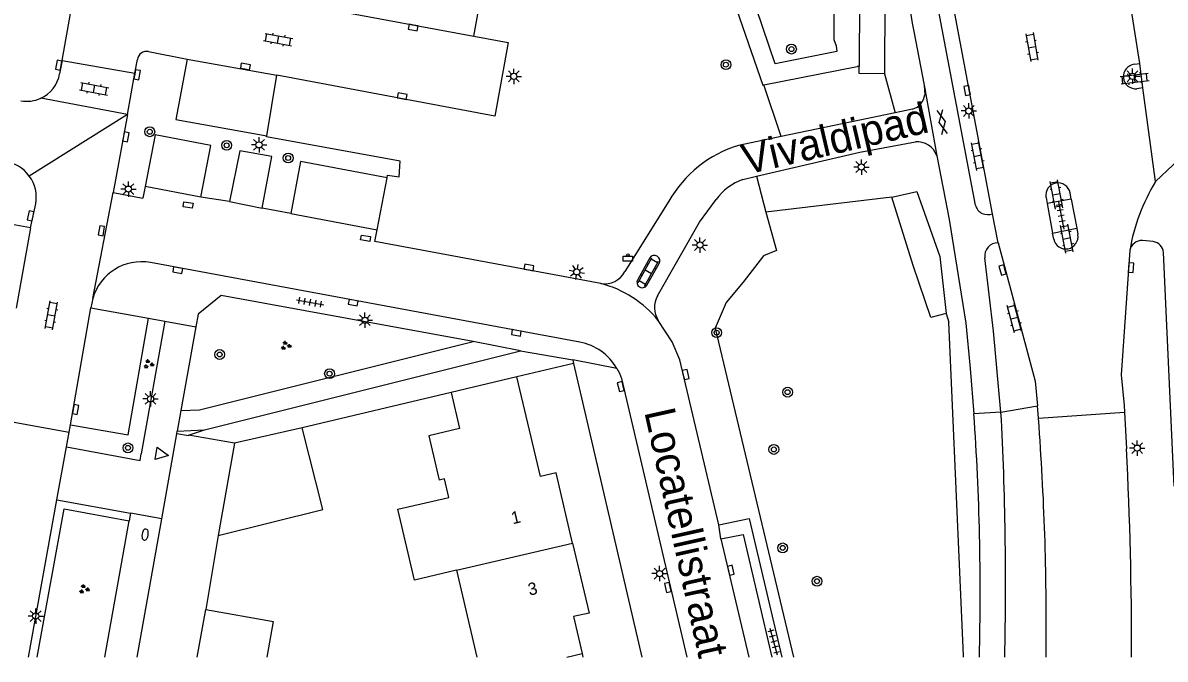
# Model space of a CAD drawing. Extents: x 133000 to 136000, y 400500 to 403500.
# Drawn here: x 133772.5 to 133865.4, y 400499.8 to 400551.6 of the extents above; entities that cross this region are included whole.
import ezdxf

# ---------------------------------------------------------------- set-up
doc = ezdxf.new("R2010")
doc.units = 0
for name, color, linetype in [('gg-afsc-erfafscheiding', 7, 'Continuous'), ('gg-afsc-muur', 7, 'Continuous'), ('gg-anno-huisnummerreeks BGT', 7, 'Continuous'), ('gg-anno-openbare ruimte label', 7, 'Continuous'), ('gg-bbg-bijgebouw', 7, 'Continuous'), ('gg-bbg-gedigitaliseerde bebouwing', 7, 'Continuous'), ('gg-bbg-hoofdgebouw', 7, 'Continuous'), ('gg-bbg-tussenscheiding', 7, 'Continuous'), ('gg-knt-verharding', 7, 'Continuous'), ('gg-knt-verharding nz', 7, 'Continuous'), ('gg-kntw-greppel-droge sloot', 7, 'Continuous'), ('gt-grn-groengrens', 7, 'Continuous'), ('gt-grn-weggrens', 7, 'Continuous'), ('gt-symb-afvalbak', 7, 'Continuous'), ('gt-symb-boom', 7, 'Continuous'), ('gt-symb-brandkraan', 7, 'Continuous'), ('gt-symb-gesloten verharding', 7, 'Continuous'), ('gt-symb-groenvak', 7, 'Continuous'), ('gt-symb-klinker verharding', 7, 'Continuous'), ('gt-symb-kolk', 7, 'Continuous'), ('gt-symb-kolk center center', 7, 'Continuous'), ('gt-symb-lichtmast', 7, 'Continuous'), ('gt-symb-tegel verharding', 7, 'Continuous'), ('gt-symb-waterafsluiter', 7, 'Continuous')]:
    doc.layers.add(name, color=color, linetype=linetype)

# ---------------------------------------------------------------- blocks, each defined once
blk = doc.blocks.new('gt0-TEG1')
at = {"layer": 'gt-symb-tegel verharding'}
for p, q in [((-1.125, 0), (1.125, 0)), ((-0.9, -0.25), (-0.9, 0.25)), ((-0.45, -0.25), (-0.45, 0.25)), ((0, -0.25), (0, 0.25)), ((0.45, -0.25), (0.45, 0.25)), ((0.9, -0.25), (0.9, 0.25))]:
    blk.add_line(p, q, dxfattribs=at)
blk = doc.blocks.new('gt0-BOOM')
at = {"layer": 'gt-symb-boom'}
for radius in [0.4, 0.2]:
    blk.add_circle((0, 0), radius, dxfattribs=at)
blk = doc.blocks.new('gt0-LMAST')
at = {"layer": 'gt-symb-lichtmast'}
for p, q in [((-0.182, 0.173), (-0.447, 0.438)), ((-0.005, 0.246), (-0.005, 0.621)), ((0.172, 0.173), (0.437, 0.438)), ((-0.255, -0.004), (-0.63, -0.004)), ((-0.182, -0.181), (-0.447, -0.446)), ((-0.005, -0.254), (-0.005, -0.629)), ((0.437, -0.446), (0.172, -0.181)), ((0.245, -0.004), (0.62, -0.004))]:
    blk.add_line(p, q, dxfattribs=at)
blk.add_circle((-0.005, -0.004), 0.25, dxfattribs=at)
blk = doc.blocks.new('gt0-KOLK')
at = {"layer": 'gt-symb-kolk'}
blk.add_lwpolyline([(0, 0), (0.375, 0), (0.375, 0.4), (-0.375, 0.4), (-0.375, 0), (0, 0)], dxfattribs=at)
blk = doc.blocks.new('gt0-KL1')
at = {"layer": 'gt-symb-klinker verharding'}
for p, q in [((-1.15, 0.3), (1.15, 0.3)), ((-1, -0.3), (-1, 0.3)), ((-0.5, 0.3), (-0.5, 0.45)), ((0, -0.3), (0, 0.3)), ((0.5, 0.3), (0.5, 0.45)), ((1, -0.3), (1, 0.3)), ((-1.15, -0.3), (1.15, -0.3)), ((-0.5, -0.45), (-0.5, -0.3)), ((0.5, -0.45), (0.5, -0.3))]:
    blk.add_line(p, q, dxfattribs=at)
blk = doc.blocks.new('gt0-GESVH1')
at = {"layer": 'gt-symb-gesloten verharding'}
for p, q in [((-0.992, -0.261), (0.008, 0.239)), ((0.008, -0.261), (-0.992, 0.239)), ((0.008, 0.239), (1.008, -0.261)), ((1.008, 0.239), (0.008, -0.261))]:
    blk.add_line(p, q, dxfattribs=at)
blk = doc.blocks.new('gt0-ABAK')
at = {"layer": 'gt-symb-afvalbak'}
blk.add_lwpolyline([(0.375, -0.5), (-0.375, -0.5), (-0.375, -0.1), (0.375, -0.1)], close=True, dxfattribs=at)
blk.add_circle((0, 0), 0.1, dxfattribs=at)
blk = doc.blocks.new('gt0-KOLKCC')
at = {"layer": 'gt-symb-kolk center center'}
blk.add_lwpolyline([(-0.375, 0.2), (0.375, 0.2), (0.375, -0.2), (-0.375, -0.2)], close=True, dxfattribs=at)
blk = doc.blocks.new('gt0-GRVAK')
at = {"layer": 'gt-symb-groenvak'}
for p, q in [((-0.11, 0.189), (-0.228, 0.24)), ((-0.182, 0.153), (0.088, 0.153)), ((-0.091, 0.211), (-0.156, 0.322)), ((-0.047, 0.214), (-0.047, 0.393)), ((-0.004, 0.211), (0.061, 0.322)), ((0.015, 0.189), (0.133, 0.24)), ((0.262, -0.052), (0.197, 0.059)), ((0.305, -0.049), (0.305, 0.13)), ((0.349, -0.052), (0.414, 0.059)), ((-0.245, -0.228), (-0.363, -0.177)), ((-0.318, -0.264), (-0.047, -0.264)), ((-0.226, -0.206), (-0.291, -0.095)), ((-0.183, -0.203), (-0.183, -0.024)), ((-0.139, -0.206), (-0.074, -0.095)), ((-0.12, -0.228), (-0.002, -0.177)), ((0.243, -0.074), (0.125, -0.023)), ((0.17, -0.11), (0.441, -0.11)), ((0.368, -0.074), (0.486, -0.023))]:
    blk.add_line(p, q, dxfattribs=at)
blk = doc.blocks.new('gt0-WAFSL')
at = {"layer": 'gt-symb-waterafsluiter'}
for p, q in [((-0.5, -0.333), (0, 0.667)), ((0, 0.667), (0.5, -0.333)), ((0.5, -0.333), (-0.5, -0.333))]:
    blk.add_line(p, q, dxfattribs=at)
blk = doc.blocks.new('gt0-BR')
at = {"layer": 'gt-symb-brandkraan'}
for centre, radius, start, end in [((-0.244, 0), 0.206, 107.56694, 252.43307), ((0.599, -2.664), 3, 106.89205, 107.56694), ((0, -0.691), 0.938, 73.10799, 106.89205), ((-0.599, -2.664), 3, 72.43309, 73.10799), ((0.244, 0), 0.206, 287.56695, 72.43309), ((0.599, 2.664), 3, 252.43307, 253.10797), ((0, 0.691), 0.938, 253.10797, 286.89206), ((-0.599, 2.664), 3, 286.89206, 287.56695)]:
    blk.add_arc(centre, radius, start, end, dxfattribs=at)

msp = doc.modelspace()

# ---------------------------------------------------------------- linework, layer by layer
at = {"layer": 'gg-afsc-erfafscheiding'}
for p, q in [((133786.01, 400518.042), (133786, 400517.983)), ((133789.751, 400517.384), (133786.01, 400518.042))]:
    msp.add_line(p, q, dxfattribs=at)
at = {"layer": 'gg-afsc-muur'}
for p, q in [((133807.366, 400521.512), (133795.27, 400518.65)), ((133788.432, 400509.9), (133787.418, 400503.888))]:
    msp.add_line(p, q, dxfattribs=at)
at = {"layer": 'gg-bbg-bijgebouw'}
for p, q in [((133795.27, 400518.65), (133789.751, 400517.384)), ((133789.751, 400517.384), (133788.432, 400509.9))]:
    msp.add_line(p, q, dxfattribs=at)
msp.add_lwpolyline([(133788.432, 400509.9), (133796.924, 400511.996), (133795.27, 400518.65)], dxfattribs=at)
at = {"layer": 'gg-bbg-gedigitaliseerde bebouwing'}
for p, q in [((133807.805, 400507.063), (133809.472, 400500)), ((133792.411, 400500), (133792.928, 400502.888))]:
    msp.add_line(p, q, dxfattribs=at)
msp.add_lwpolyline([(133807.805, 400507.063), (133804.399, 400506.259), (133803.04, 400512.018), (133807.174, 400512.988), (133806.833, 400514.484), (133806.394, 400514.384)], dxfattribs=at)
at = {"layer": 'gg-bbg-hoofdgebouw'}
for p, q in [((133812.726, 400522.782), (133807.366, 400521.512)), ((133786.713, 400500), (133787.418, 400503.888)), ((133787.418, 400503.888), (133792.928, 400502.888)), ((133818.017, 400500.291), (133818.084, 400500))]:
    msp.add_line(p, q, dxfattribs=at)
for points in [[(133817.245, 400509.279), (133815.903, 400514.98), (133814.642, 400514.686), (133812.726, 400522.782)], [(133807.366, 400521.512), (133808.061, 400518.587), (133805.56, 400517.995), (133806.394, 400514.384)], [(133817.245, 400509.279), (133818.587, 400503.58), (133817.32, 400503.299), (133818.017, 400500.291)]]:
    msp.add_lwpolyline(points, dxfattribs=at)
at = {"layer": 'gg-bbg-tussenscheiding'}
for p, q in [((133807.805, 400507.063), (133817.245, 400509.279)), ((133816.777, 400500), (133818.017, 400500.291))]:
    msp.add_line(p, q, dxfattribs=at)
at = {"layer": 'gg-knt-verharding'}
for p, q in [((133851.417, 400536.044), (133847.8, 400555.165)), ((133850.01, 400536.732), (133846.76, 400553.991)), ((133775.726, 400548.489), (133776.555, 400553.068)), ((133863.388, 400548.254), (133862.64, 400553.06)), ((133845.002, 400550.846), (133845.84, 400546.486)), ((133775.726, 400548.489), (133775.53, 400547.403)), ((133775.726, 400548.489), (133781.657, 400547.475)), ((133781.657, 400547.475), (133781.859, 400548.581)), ((133782.767, 400549.214), (133785.905, 400548.609)), ((133781.041, 400544.098), (133781.657, 400547.475)), ((133862.942, 400548.189), (133863.388, 400548.254)), ((133863.637, 400546.262), (133863.388, 400548.254)), ((133792.385, 400542.382), (133793.189, 400547.312)), ((133845.84, 400546.486), (133845.887, 400545.709)), ((133863.637, 400546.262), (133863.144, 400546.198)), ((133864.671, 400538.65), (133863.637, 400546.262)), ((133781.041, 400544.098), (133773.99, 400545.424)), ((133781.041, 400544.098), (133779.884, 400537.753)), ((133843.489, 400544.246), (133834.219, 400542.318)), ((133844.907, 400544.541), (133843.489, 400544.246)), ((133834.219, 400542.318), (133830.753, 400541.597)), ((133782.48, 400538.263), (133782.294, 400537.304)), ((133801.345, 400534.725), (133802.159, 400538.969)), ((133831.096, 400538.829), (133832.213, 400539.088)), ((133779.884, 400537.753), (133782.294, 400537.304)), ((133789.357, 400537.024), (133787.027, 400537.379)), ((133855.755, 400537.358), (133855.849, 400536.862)), ((133857.791, 400537.235), (133857.723, 400537.736)), ((133773.171, 400534.894), (133773.583, 400536.839)), ((133794.341, 400536.068), (133792.005, 400536.502)), ((133825.087, 400537.059), (133821.495, 400531.333)), ((133857.791, 400537.235), (133855.849, 400536.862)), ((133855.849, 400536.862), (133856.282, 400534.472)), ((133857.791, 400537.235), (133858.254, 400534.872)), ((133773.171, 400534.894), (133770.268, 400535.415)), ((133851.856, 400533.669), (133851.417, 400536.044)), ((133801.166, 400533.789), (133801.345, 400534.725)), ((133856.282, 400534.472), (133858.254, 400534.872)), ((133856.381, 400533.976), (133856.282, 400534.472)), ((133858.254, 400534.872), (133858.344, 400534.347)), ((133819.557, 400530.363), (133801.166, 400533.789)), ((133864.478, 400533.778), (133863.598, 400533.872)), ((133866.169, 400513.909), (133865.303, 400532.883)), ((133817.836, 400525.611), (133782.922, 400532.066)), ((133823.529, 400532.459), (133822.547, 400530.687)), ((133823.299, 400530.223), (133824.301, 400531.984)), ((133778.228, 400529.138), (133778.076, 400528.39)), ((133778.076, 400528.39), (133782.769, 400527.541)), ((133784.09, 400527.302), (133782.166, 400516.516)), ((133782.769, 400527.541), (133784.09, 400527.302)), ((133786.602, 400526.847), (133785.399, 400520.059)), ((133787.307, 400518.487), (133813.025, 400524.905)), ((133813.025, 400524.905), (133817.27, 400524.168)), ((133817.338, 400523.875), (133812.726, 400522.782)), ((133817.27, 400524.168), (133817.338, 400523.875)), ((133817.338, 400523.875), (133822.893, 400500)), ((133852.091, 400519.924), (133855.056, 400520.42)), ((133855.148, 400519.416), (133855.056, 400520.42)), ((133855.148, 400519.416), (133862.135, 400519.911)), ((133862.135, 400519.911), (133862.297, 400516.943)), ((133770.368, 400519.371), (133776.299, 400518.278)), ((133776.299, 400518.278), (133776.409, 400518.878)), ((133855.186, 400518.749), (133855.148, 400519.416)), ((133776.083, 400517.095), (133776.299, 400518.278)), ((133783.838, 400511.245), (133785.062, 400518.145)), ((133785.062, 400518.145), (133785.101, 400518.372)), ((133786, 400517.983), (133785.062, 400518.145)), ((133785.101, 400518.372), (133787.307, 400518.487)), ((133775.294, 400512.788), (133776.083, 400517.095)), ((133773.006, 400500), (133775.294, 400512.788)), ((133775.294, 400512.788), (133781.307, 400511.702)), ((133781.307, 400511.702), (133781.197, 400511.088)), ((133781.823, 400500), (133783.838, 400511.245)), ((133779.217, 400500), (133781.197, 400511.088)), ((133829.311, 400509.626), (133829.136, 400510.745))]:
    msp.add_line(p, q, dxfattribs=at)
for points in [[(133809.227, 400550.474), (133810.12, 400555.398), (133798.732, 400557.483)], [(133809.227, 400550.474), (133812.011, 400549.962), (133810.937, 400543.963), (133793.189, 400547.312)], [(133785.905, 400548.609), (133784.985, 400543.71), (133792.385, 400542.382)], [(133787.027, 400537.379), (133787.821, 400541.596), (133783.295, 400542.455), (133782.48, 400538.263)], [(133832.213, 400539.088), (133840.605, 400541.032), (133845.129, 400541.888)], [(133792.005, 400536.502), (133792.795, 400540.696), (133790.196, 400541.16), (133789.357, 400537.024)], [(133802.159, 400538.969), (133795.128, 400540.276), (133794.341, 400536.068)], [(133846.872, 400540.755), (133847.882, 400535.57), (133849.226, 400527.151), (133849.59, 400523.462), (133849.887, 400519.767)], [(133824.161, 400529.374), (133827.561, 400535.348), (133828.924, 400537.185)], [(133851.856, 400533.669), (133854.879, 400522.431), (133855.056, 400520.42)], [(133862.579, 400533.085), (133861.863, 400522.937), (133862.119, 400520.441), (133862.135, 400519.911)], [(133852.091, 400519.924), (133851.497, 400526.502), (133850.788, 400532.465)], [(133809.166, 400525.643), (133788.676, 400529.405), (133786.787, 400527.89), (133786.602, 400526.847)], [(133776.409, 400518.878), (133781.113, 400518.059), (133782.769, 400527.541)], [(133829.136, 400510.745), (133825.965, 400524.167), (133825.362, 400525.625), (133824.217, 400527.36)], [(133785.399, 400520.059), (133786.9, 400520.115), (133809.166, 400525.643)], [(133820.85, 400523.471), (133821.057, 400523.071), (133821.221, 400522.656), (133826.53, 400500)], [(133776.083, 400517.095), (133782.068, 400515.974), (133782.166, 400516.516)], [(133829.136, 400510.745), (133831.612, 400511.284), (133834.268, 400500)], [(133829.311, 400509.626), (133831.125, 400509.968), (133833.451, 400500)]]:
    msp.add_lwpolyline(points, dxfattribs=at)
for centre, radius, start, end in [((133936.334, 400566.797), 92.715, 182.95718, 189.90674), ((133782.601, 400548.484), 0.749, 77.20417, 172.55935), ((133863.047, 400547.194), 1.001, 95.99585, 275.59057), ((133772.874, 400547.881), 2.699, 294.42643, 349.79555), ((133844.512, 400545.867), 1.384, 286.56929, 353.43464), ((133772.874, 400547.868), 2.687, 259.39465, 294.54887), ((133845.26, 400540.183), 1.71, 19.54584, 94.40411), ((133833.561, 400532.285), 9.726, 106.78016, 150.60355), ((133770.691, 400537.368), 2.94, 36.1424, 82.66632), ((133770.691, 400537.368), 2.94, 349.63893, 36.14682), ((133832.681, 400534.478), 4.631, 110.01945, 144.22515), ((133856.74, 400537.541), 1.002, 100.88779, 190.51713), ((133856.74, 400537.541), 1.002, 11.224, 100.87847), ((133877.625, 400530.605), 15.249, 148.15659, 170.63883), ((133851.016, 400537.007), 1.043, 195.29358, 292.59066), ((133851.818, 400532.627), 1.043, 87.91695, 188.93423), ((133857.36, 400534.178), 0.999, 191.65091, 280.69677), ((133857.359, 400534.178), 0.999, 280.71067, 9.75419), ((133863.582, 400532.84), 1.032, 89.09958, 166.26009), ((133864.315, 400532.8), 0.991, 4.79333, 80.54563), ((133823.902, 400532.2), 0.454, 331.51386, 145.27942), ((133782.177, 400528.034), 4.1, 79.53187, 164.3779), ((133819.838, 400532.223), 1.881, 261.41536, 331.76203), ((133817.388, 400521.88), 8.756, 38.74576, 75.65711), ((133822.927, 400530.462), 0.442, 149.37905, 327.27001), ((133825.895, 400528.414), 1.982, 151.04293, 212.14251), ((133816.991, 400521.228), 4.464, 30.16544, 79.08354), ((133645.873, 400505.255), 204.529, 358.52783, 4.06883), ((133594.572, 400505.966), 257.897, 358.6745, 3.10255), ((133639.127, 400502.797), 216.647, 359.26019, 4.2225), ((133558.444, 400501.006), 304.27, 359.81058, 3.00241)]:
    msp.add_arc(centre, radius, start, end, dxfattribs=at)
at = {"layer": 'gg-knt-verharding nz'}
for p, q in [((133797.799, 400552.576), (133809.227, 400550.474)), ((133785.905, 400548.609), (133793.189, 400547.312)), ((133787.027, 400537.379), (133782.48, 400538.263)), ((133789.357, 400537.024), (133792.005, 400536.502)), ((133794.341, 400536.068), (133801.345, 400534.725)), ((133773.171, 400534.894), (133771.991, 400528.361)), ((133776.409, 400518.878), (133778.076, 400528.39)), ((133829.311, 400509.626), (133831.585, 400500))]:
    msp.add_line(p, q, dxfattribs=at)
at = {"layer": 'gg-kntw-greppel-droge sloot'}
for points in [[(133815.981, 400625.372), (133823.988, 400610.354), (133829.558, 400599.348), (133834.898, 400585.715), (133839.268, 400573.096), (133840.434, 400568.391), (133839.988, 400561.841), (133840.581, 400553.482), (133840.559, 400548.012)], [(133818.311, 400625.403), (133826, 400611.48), (133831.352, 400600.192), (133837.154, 400586.424), (133841.482, 400573.031), (133842.196, 400568.363), (133842.056, 400561.794), (133842.641, 400553.475), (133842.617, 400547.415)], [(133842.617, 400547.415), (133840.557, 400547.424), (133840.559, 400548.012)], [(133843.213, 400537.383), (133845.241, 400537.85), (133847.13, 400532.564), (133847.624, 400527.936)], [(133847.624, 400527.936), (133846.388, 400527.598), (133844.957, 400531.838), (133843.213, 400537.383)]]:
    msp.add_lwpolyline(points, dxfattribs=at)
at = {"layer": 'gt-grn-groengrens'}
for p, q in [((133832.792, 400546.504), (133840.397, 400548.013)), ((133840.559, 400548.012), (133840.397, 400548.013)), ((133842.617, 400547.415), (133843.489, 400544.246)), ((133834.219, 400542.318), (133832.792, 400546.504)), ((133832.213, 400539.088), (133832.959, 400536.169)), ((133843.213, 400537.383), (133832.959, 400536.169)), ((133847.624, 400527.936), (133847.864, 400527.238)), ((133786.01, 400518.042), (133787.307, 400518.487))]:
    msp.add_line(p, q, dxfattribs=at)
for points in [[(133808.748, 400621.835), (133814.615, 400624.656), (133815.558, 400622.929), (133821.482, 400612.502), (133825.299, 400604.784), (133828.014, 400598.464), (133831.209, 400591.121), (133833.589, 400584.639), (133836.303, 400575.871), (133837.245, 400572.661), (133838.016, 400568.923), (133838.326, 400564.566), (133838.326, 400560.618), (133838.486, 400560.413), (133838.486, 400550.19), (133838.681, 400549.693), (133838.74, 400549.213), (133833.728, 400548.219), (133811.287, 400614.354), (133811.416, 400614.843), (133811.104, 400614.892), (133808.748, 400621.835)], [(133820.157, 400582.782), (133832.73, 400546.492), (133832.792, 400546.504)], [(133802.159, 400538.969), (133802.186, 400539.165), (133803.15, 400539.032), (133803.215, 400540.302), (133792.366, 400542.277), (133792.385, 400542.382)], [(133832.959, 400536.169), (133833.844, 400533.06), (133832.784, 400532.605), (133831.118, 400530.483), (133829.754, 400528.816), (133828.845, 400526.728), (133835.205, 400500)], [(133849.033, 400500), (133849.042, 400500.139), (133847.864, 400527.238)], [(133773.696, 400500), (133775.896, 400512.055), (133781.197, 400511.088)]]:
    msp.add_lwpolyline(points, dxfattribs=at)
at = {"layer": 'gt-grn-weggrens'}
for p, q in [((133845.84, 400546.486), (133846.872, 400540.755)), ((133781.041, 400544.098), (133773.065, 400539.102)), ((133867.769, 400541.596), (133864.671, 400538.65)), ((133778.228, 400529.138), (133779.884, 400537.753)), ((133784.09, 400527.302), (133786.602, 400526.847)), ((133813.025, 400524.905), (133809.166, 400525.643)), ((133820.85, 400523.471), (133817.27, 400524.168)), ((133785.399, 400520.059), (133785.101, 400518.372)), ((133852.091, 400519.924), (133849.887, 400519.767)), ((133783.838, 400511.245), (133781.307, 400511.702))]:
    msp.add_line(p, q, dxfattribs=at)

# ---------------------------------------------------------------- block references
at = {"layer": 'gt-symb-afvalbak'}
msp.add_blockref('gt0-ABAK', (133821.748, 400532.69), dxfattribs=at)
at = {"layer": 'gt-symb-boom'}
for p in [(133835.049, 400549.421), (133829.722, 400548.151), (133782.862, 400542.7), (133789.114, 400541.599), (133794.12, 400540.572), (133828.965, 400526.379), (133788.549, 400524.6), (133797.485, 400523.037), (133834.738, 400521.538), (133781.087, 400517.011), (133833.617, 400516.885), (133834.34, 400508.88), (133837.132, 400506.171)]:
    msp.add_blockref('gt0-BOOM', p, dxfattribs=at)
at = {"layer": 'gt-symb-brandkraan', "rotation": 80.55652508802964}
msp.add_blockref('gt0-BR', (133782.48, 400509.967), dxfattribs=at)
at = {"layer": 'gt-symb-gesloten verharding', "rotation": -79.16208955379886}
msp.add_blockref('gt0-GESVH1', (133847.312, 400543.501), dxfattribs=at)
at = {"layer": 'gt-symb-groenvak'}
for p in [(133793.921, 400525.32), (133782.758, 400523.817), (133777.513, 400505.525)]:
    msp.add_blockref('gt0-GRVAK', p, dxfattribs=at)
at = {"layer": 'gt-symb-klinker verharding'}
for p, rotation in [((133793.309, 400550.19), -10.602058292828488), ((133854.606, 400549.586), -79.85920685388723), ((133862.966, 400547.032), 6.719879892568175), ((133778.337, 400546.193), -10.602058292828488), ((133850.197, 400540.734), 100.8941829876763), ((133856.618, 400537.6), 100.89418298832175), ((133857.458, 400534.013), 100.89418298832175), ((133823.408, 400531.314), 60.9732337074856), ((133774.849, 400527.778), 79.6900296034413), ((133853.182, 400527.537), 105.00891367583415)]:
    msp.add_blockref('gt0-KL1', p, dxfattribs=dict(at, rotation=rotation))
at = {"layer": 'gt-symb-kolk'}
for p, rotation in [((133804.32, 400551.377), 169.57734546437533), ((133775.652, 400548.083), 79.92566727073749), ((133781.645, 400547.377), -100.60205829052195), ((133790.602, 400547.804), -10.658361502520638), ((133803.348, 400545.395), -10.54573436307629), ((133849.536, 400546.095), 100.60205829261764), ((133780.718, 400542.328), -100.30997039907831), ((133773.367, 400535.837), 78.22937399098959), ((133779.125, 400534.623), 79.74640197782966), ((133785.171, 400531.649), 169.5773454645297), ((133813.666, 400531.477), -10.54573436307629), ((133852.415, 400531.513), 105.18978717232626), ((133862.472, 400531.678), -94.07336449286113), ((133799.443, 400529.011), 169.57734546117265), ((133812.711, 400526.56), 169.57734546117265), ((133826.258, 400522.929), -76.70041567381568), ((133821.362, 400522.035), 103.17492660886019), ((133776.635, 400520.165), -99.9615165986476), ((133829.929, 400507.018), -76.70041567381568), ((133825.19, 400505.712), 103.17492660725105)]:
    msp.add_blockref('gt0-KOLK', p, dxfattribs=dict(at, rotation=rotation))
at = {"layer": 'gt-symb-kolk center center'}
for p, rotation in [((133785.98, 400536.752), 171.83749053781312), ((133800.415, 400534.051), 171.08396326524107)]:
    msp.add_blockref('gt0-KOLKCC', p, dxfattribs=dict(at, rotation=rotation))
at = {"layer": 'gt-symb-lichtmast'}
for p in [(133812.475, 400547.207), (133862.794, 400547.213), (133849.481, 400544.397), (133791.754, 400541.643), (133840.744, 400539.838), (133781.127, 400538.044), (133827.617, 400533.5), (133800.362, 400527.39), (133782.927, 400520.998), (133863.177, 400516.992), (133824.332, 400506.796), (133773.592, 400503.339)]:
    msp.add_blockref('gt0-LMAST', p, dxfattribs=at)
at = {"layer": 'gt-symb-lichtmast', "rotation": 169.4542656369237}
msp.add_blockref('gt0-LMAST', (133817.589, 400531.309), dxfattribs=at)
at = {"layer": 'gt-symb-tegel verharding'}
for p, rotation in [((133856.989, 400535.897), -79.34163849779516), ((133795.911, 400528.84), -10.32023339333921), ((133833.611, 400501.249), 105.42597037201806)]:
    msp.add_blockref('gt0-TEG1', p, dxfattribs=dict(at, rotation=rotation))
at = {"layer": 'gt-symb-waterafsluiter', "rotation": -100.1407931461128}
msp.add_blockref('gt0-WAFSL', (133783.716, 400516.512), dxfattribs=at)

# ---------------------------------------------------------------- texts
at = {"layer": 'gg-anno-huisnummerreeks BGT'}
for s, p in [('1', (133812.38, 400510.797)), ('3', (133813.746, 400504.994))]:
    msp.add_text(s, height=1, rotation=13.2, dxfattribs=at).set_placement(p)
at = {"layer": 'gg-anno-openbare ruimte label'}
for s, rotation, p in [('Vivaldipad', 13.1, (133831.345, 400539.196)), ('Locatellistraat', 282.5, (133823.071, 400519.952))]:
    msp.add_text(s, height=2.5, rotation=rotation, dxfattribs=at).set_placement(p)

doc.saveas('drawing.dxf')
